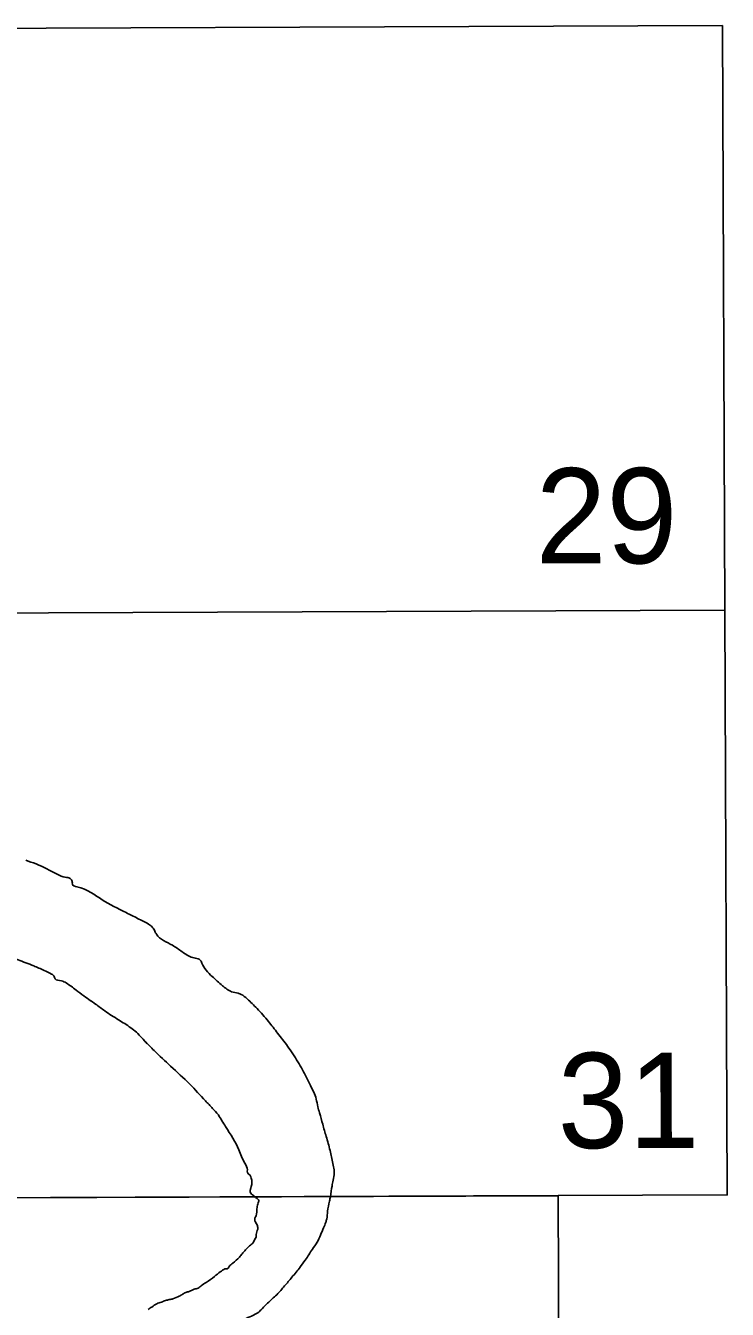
# Model space of a CAD drawing. Extents: x 3329332 to 3367211, y 631066 to 656469.
# Drawn here: x 3355661 to 3356522, y 633892 to 635469 of the extents above; entities that cross this region are included whole.
import ezdxf

# ---------------------------------------------------------------- set-up
doc = ezdxf.new("R2010")
doc.units = 0
doc.layers.add('V-ANNO-NPLT', color=7, linetype='Continuous')

msp = doc.modelspace()

# ---------------------------------------------------------------- linework, layer by layer
at = {"layer": 'V-ANNO-NPLT'}
for points in [[(3355273, 634745.8), (3356519.5, 634750.5), (3356516.4, 635468.7), (3355270.6, 635464), (3355273, 634745.8)], [(3355275.4, 634027.5), (3356522.5, 634032.3), (3356519.5, 634750.5), (3355273, 634745.8), (3355275.4, 634027.5)], [(3355069.9, 633308.7), (3356317.6, 633313.2), (3356314.7, 634031.4), (3355067.6, 634026.9), (3355069.9, 633308.7)]]:
    msp.add_lwpolyline(points, dxfattribs=at)
for points in [[(3355660.8, 634443.5), (3355673.6, 634438.9), (3355699.4, 634426.3), (3355709.2, 634422.6), (3355715.3, 634421.2), (3355717.2, 634419.3), (3355718.1, 634415.5), (3355718.1, 634414.1), (3355723.8, 634410.9), (3355754.7, 634395), (3355784.2, 634379.1), (3355798.2, 634372.1)], [(3355798.2, 634372.1), (3355811.6, 634365.1), (3355816.3, 634361.4), (3355819.5, 634356.3), (3355821.4, 634352.5), (3355841.1, 634339), (3355852.8, 634331), (3355865.9, 634324), (3355872.5, 634322.2), (3355874.8, 634321.2), (3355876.2, 634319.4), (3355877.2, 634317), (3355889.8, 634300.7), (3355902.5, 634289.4), (3355913.7, 634282), (3355921.7, 634280.1), (3355925.4, 634278.7), (3355932.9, 634273.1)], [(3355610, 634340.4), (3355628.5, 634332.5), (3355634.1, 634330.2), (3355639.7, 634326.9), (3355651.4, 634321.3), (3355670.6, 634313.8), (3355683.3, 634308.2), (3355692.6, 634303.6), (3355695.9, 634300.8), (3355696.8, 634298), (3355704.8, 634295.2), (3355710.4, 634292.8), (3355722.6, 634284), (3355732, 634276.9), (3355740.4, 634270.9)], [(3355738.7, 634272.1), (3355746.7, 634266.7), (3355758, 634258.3), (3355774.8, 634247.5), (3355789.8, 634237.7), (3355796.8, 634232.1), (3355810, 634218.1)], [(3355932.9, 634273.1), (3355944.9, 634261.4), (3355958.9, 634245.5), (3355970.2, 634231), (3355982.4, 634215.1), (3355995, 634196), (3356000.7, 634186.1), (3356010.5, 634166.9), (3356017.6, 634150.1), (3356019.5, 634140.7), (3356021.8, 634133.2)], [(3355806.9, 634221.4), (3355818.6, 634209.7), (3355838.8, 634190.5), (3355862.2, 634168.5), (3355881.5, 634148), (3355890.4, 634138.6), (3355897.4, 634130.7)], [(3355897.4, 634130.7), (3355906.3, 634116.2), (3355922.7, 634087.6), (3355929.8, 634071.3), (3355933.1, 634063.3), (3355933.1, 634060), (3355934, 634058.6), (3355936.4, 634056.3), (3355937.3, 634054.4), (3355938.7, 634049.3), (3355937.3, 634040.8), (3355936.4, 634037.1), (3355936.4, 634035.7), (3355938.3, 634033.3), (3355942.5, 634030)], [(3356021.8, 634133.2), (3356025.6, 634119.2), (3356029.8, 634104.2), (3356034.6, 634086.9), (3356037.9, 634071), (3356039.7, 634063), (3356039.8, 634059.3), (3356038.4, 634050.4), (3356037, 634043.3), (3356035.1, 634030.2)], [(3355923.2, 633956), (3355926.5, 633960.1), (3355930.9, 633964.8), (3355935.8, 633969.8), (3355939.7, 633973.1), (3355942.4, 633977.8), (3355943.8, 633980.3), (3355944, 633983.6), (3355944.6, 633986.9), (3355945.7, 633990.2), (3355945.4, 633994.4), (3355942.9, 633999.1), (3355942.1, 634000.7), (3355943.7, 634006.8), (3355944.8, 634015.3), (3355945.9, 634021.1), (3355946.7, 634023.9), (3355947, 634025.5), (3355944, 634028.6), (3355942.5, 634030)], [(3356035.1, 634030.2), (3356033.8, 634024.6), (3356031.6, 634012.2), (3356030.5, 634002.8), (3356029.4, 633998.7), (3356026.7, 633992.1), (3356022.8, 633982.9), (3356018.7, 633974.4), (3356012.9, 633965.6), (3356004.2, 633952.3), (3355997.6, 633943.2)], [(3355923.2, 633956), (3355915, 633948.5), (3355910.6, 633944.4), (3355909.5, 633942.5), (3355906.5, 633941.4), (3355905.4, 633941.4), (3355902.7, 633940), (3355899.6, 633937.8), (3355892.8, 633932.2), (3355882.3, 633924.8), (3355876.8, 633920.9), (3355872.7, 633917.9), (3355867.7, 633916.5), (3355864.4, 633915.1), (3355862.2, 633914)], [(3355997.8, 633943.5), (3355987.8, 633931.3), (3355978.7, 633920.5), (3355969.1, 633909.8), (3355957.8, 633899.3), (3355951.5, 633892.9)], [(3355862.3, 633914), (3355858.8, 633912.9), (3355857.4, 633912.6), (3355853.5, 633910.4), (3355849.4, 633907.9), (3355841.7, 633904.8), (3355837, 633903.7), (3355832.6, 633902.6), (3355827.4, 633900.7), (3355821.9, 633898.7), (3355815.6, 633894.6), (3355811.2, 633891.8)], [(3355951.5, 633892.9), (3355947, 633888.5), (3355938.2, 633883.5), (3355929.4, 633879.6), (3355923.9, 633876.6), (3355915.1, 633869.7), (3355911.5, 633867.2), (3355910.1, 633866.4), (3355907.1, 633865.8), (3355901.3, 633862.8), (3355894.7, 633859.2), (3355885.9, 633853.9), (3355879.8, 633849.5), (3355872.1, 633843.9)]]:
    msp.add_spline(points, degree=3, dxfattribs=at)

# ---------------------------------------------------------------- texts
for s, p in [('29', (3356287.2, 634808)), ('31', (3356314.2, 634089.8))]:
    msp.add_text(s, height=117, rotation=0.1083, dxfattribs=at).set_placement(p)

doc.saveas('drawing.dxf')
